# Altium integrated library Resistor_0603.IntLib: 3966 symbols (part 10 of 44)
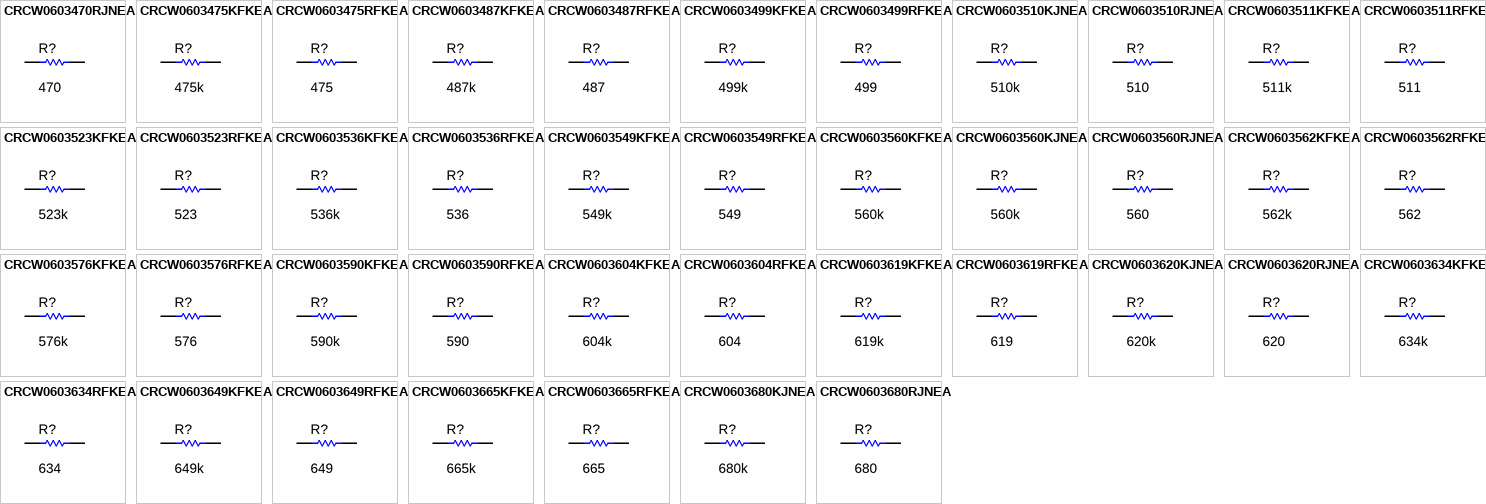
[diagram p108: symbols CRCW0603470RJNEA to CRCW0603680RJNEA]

## CRCW0603511KFKEA
designator R?  ValueDisplayed: 511k  (hidden comment: CRCW0603511KFKEA)
RES, 511 k, 1%, 0.1 W, 0603; Manufacturer: Vishay-Dale; CompType: Resistor; Value: 511k; Res_ohm: 511000; Tolerance_%: 1; Power_W: 0.1; Value2: 0.1W; VDC_V: 75; TempCo: 100 ppm/C; SizeArea_mm2: 1.28; SizeX_mm: 1.6; SizeY_mm: 0.8; EIA_Code: E96; U/M: EA; AEC Category: Q200; Green_Lifecycle: Active; Green_REACh: Passed
signal-integrity model Resistor
simulation model Resistor
footprint 0603
footprint 0603M
footprint 0603L
footprint 0603_HV
footprint 0603S
pins: 1, 2

## CRCW0603511RFKEA
designator R?  ValueDisplayed: 511  (hidden comment: CRCW0603511RFKEA)
RES, 511, 1%, 0.1 W, 0603; Manufacturer: Vishay-Dale; CompType: Resistor; Value: 511; Value_Code: 511R; Tolerance_%: 1; Power_W: 0.1; Value2: 0.1W; VDC_V: 75; TempCo: 100 ppm/C; SizeArea_mm2: 1.28; SizeX_mm: 1.6; SizeY_mm: 0.8; EIA_Code: E96; U/M: EA; AEC Category: Q200; Green_Lifecycle: Active; Green_REACh: Passed
signal-integrity model Resistor
simulation model Resistor
footprint 0603
footprint 0603M
footprint 0603L
footprint 0603_HV
footprint 0603S
pins: 1, 2

## CRCW0603523KFKEA
designator R?  ValueDisplayed: 523k  (hidden comment: CRCW0603523KFKEA)
RES, 523 k, 1%, 0.1 W, 0603; Manufacturer: Vishay-Dale; CompType: Resistor; Value: 523k; Res_ohm: 523000; Tolerance_%: 1; Power_W: 0.1; Value2: 0.1W; VDC_V: 75; TempCo: 100 ppm/C; SizeArea_mm2: 1.28; SizeX_mm: 1.6; SizeY_mm: 0.8; EIA_Code: E96; U/M: EA; AEC Category: Q200; Green_Lifecycle: Active; Green_REACh: Passed
signal-integrity model Resistor
simulation model Resistor
footprint 0603
footprint 0603M
footprint 0603L
footprint 0603_HV
footprint 0603S
pins: 1, 2

## CRCW0603523RFKEA
designator R?  ValueDisplayed: 523  (hidden comment: CRCW0603523RFKEA)
RES, 523, 1%, 0.1 W, 0603; Manufacturer: Vishay-Dale; CompType: Resistor; Value: 523; Value_Code: 523R; Tolerance_%: 1; Power_W: 0.1; Value2: 0.1W; VDC_V: 75; TempCo: 100 ppm/C; SizeArea_mm2: 1.28; SizeX_mm: 1.6; SizeY_mm: 0.8; EIA_Code: E96; U/M: EA; AEC Category: Q200
signal-integrity model Resistor
simulation model Resistor
footprint 0603
footprint 0603M
footprint 0603L
footprint 0603_HV
footprint 0603S
pins: 1, 2

## CRCW0603536KFKEA
designator R?  ValueDisplayed: 536k  (hidden comment: CRCW0603536KFKEA)
RES, 536 k, 1%, 0.1 W, 0603; Manufacturer: Vishay-Dale; CompType: Resistor; Value: 536k; Res_ohm: 536000; Tolerance_%: 1; Power_W: 0.1; Value2: 0.1W; VDC_V: 75; TempCo: 100 ppm/C; SizeArea_mm2: 1.28; SizeX_mm: 1.6; SizeY_mm: 0.8; EIA_Code: E96; U/M: EA; AEC Category: Q200
signal-integrity model Resistor
simulation model Resistor
footprint 0603
footprint 0603M
footprint 0603L
footprint 0603_HV
footprint 0603S
pins: 1, 2

## CRCW0603536RFKEA
designator R?  ValueDisplayed: 536  (hidden comment: CRCW0603536RFKEA)
RES, 536, 1%, 0.1 W, 0603; Manufacturer: Vishay-Dale; CompType: Resistor; Value: 536; Value_Code: 536R; Tolerance_%: 1; Power_W: 0.1; Value2: 0.1W; VDC_V: 75; TempCo: 100 ppm/C; SizeArea_mm2: 1.28; SizeX_mm: 1.6; SizeY_mm: 0.8; EIA_Code: E96; U/M: EA; AEC Category: Q200
signal-integrity model Resistor
simulation model Resistor
footprint 0603
footprint 0603M
footprint 0603L
footprint 0603_HV
footprint 0603S
pins: 1, 2

## CRCW0603549KFKEA
designator R?  ValueDisplayed: 549k  (hidden comment: CRCW0603549KFKEA)
RES, 549 k, 1%, 0.1 W, 0603; Manufacturer: Vishay-Dale; CompType: Resistor; Value: 549k; Res_ohm: 549000; Tolerance_%: 1; Power_W: 0.1; Value2: 0.1W; VDC_V: 75; TempCo: 100 ppm/C; SizeArea_mm2: 1.28; SizeX_mm: 1.6; SizeY_mm: 0.8; EIA_Code: E96; U/M: EA; AEC Category: Q200; Green_Lifecycle: Active; Green_REACh: Passed
signal-integrity model Resistor
simulation model Resistor
footprint 0603
footprint 0603M
footprint 0603L
footprint 0603_HV
footprint 0603S
pins: 1, 2

## CRCW0603549RFKEA
designator R?  ValueDisplayed: 549  (hidden comment: CRCW0603549RFKEA)
RES, 549, 1%, 0.1 W, 0603; Manufacturer: Vishay-Dale; CompType: Resistor; Value: 549; Value_Code: 549R; Tolerance_%: 1; Power_W: 0.1; Value2: 0.1W; VDC_V: 75; TempCo: 100 ppm/C; SizeArea_mm2: 1.28; SizeX_mm: 1.6; SizeY_mm: 0.8; EIA_Code: E96; U/M: EA; AEC Category: Q200; Green_Lifecycle: Active; Green_REACh: Passed
signal-integrity model Resistor
simulation model Resistor
footprint 0603
footprint 0603M
footprint 0603L
footprint 0603_HV
footprint 0603S
pins: 1, 2

## CRCW0603560KFKEA
designator R?  ValueDisplayed: 560k  (hidden comment: CRCW0603560KFKEA)
RES, 560 k, 1%, 0.1 W, AEC-Q200 Grade 0, 0603; Manufacturer: Vishay-Dale; CompType: Resistor; Value: 560k; Res_ohm: 560000; Tolerance_%: 1; Power_W: 0.1; Value2: 0.1W; VDC_V: 75; TempCo: 100 ppm/C; SizeArea_mm2: 1.28; SizeX_mm: 1.6; SizeY_mm: 0.8; U/M: EA; AEC Category: Q200; AEC Qualified: Y; AEC Grade: 0; Green_Lifecycle: Active; Green_REACh: Passed
signal-integrity model Resistor
simulation model Resistor
footprint 0603
footprint 0603M
footprint 0603L
footprint 0603_HV
footprint 0603S
pins: 1, 2

## CRCW0603560KJNEA
designator R?  ValueDisplayed: 560k  (hidden comment: CRCW0603560KJNEA)
RES, 560 k, 5%, 0.1 W, 0603; Manufacturer: Vishay-Dale; CompType: Resistor; Value: 560k; Res_ohm: 560000; Tolerance_%: 5; Power_W: 0.1; Value2: 0.1W; VDC_V: 75; TempCo: 200 ppm/C; SizeArea_mm2: 1.28; SizeX_mm: 1.6; SizeY_mm: 0.8; SizeZ_mm: 1; EIA_Code: E24; U/M: EA; AEC Category: Q200
signal-integrity model Resistor
simulation model Resistor
footprint 0603
footprint 0603M
footprint 0603L
footprint 0603_HV
footprint 0603S
pins: 1, 2

## CRCW0603560RJNEA
designator R?  ValueDisplayed: 560  (hidden comment: CRCW0603560RJNEA)
RES, 560, 5%, 0.1 W, 0603; Manufacturer: Vishay-Dale; CompType: Resistor; Value: 560; Value_Code: 560R; Tolerance_%: 5; Power_W: 0.1; Value2: 0.1W; VDC_V: 75; TempCo: 200 ppm/C; SizeArea_mm2: 1.28; SizeX_mm: 1.6; SizeY_mm: 0.8; SizeZ_mm: 1; EIA_Code: E24; U/M: EA; AEC Category: Q200; Green_Lifecycle: Active; Green_REACh: Passed
signal-integrity model Resistor
simulation model Resistor
footprint 0603
footprint 0603M
footprint 0603L
footprint 0603_HV
footprint 0603S
pins: 1, 2

## CRCW0603562KFKEA
designator R?  ValueDisplayed: 562k  (hidden comment: CRCW0603562KFKEA)
RES, 562 k, 1%, 0.1 W, 0603; Manufacturer: Vishay-Dale; CompType: Resistor; Value: 562k; Res_ohm: 562000; Tolerance_%: 1; Power_W: 0.1; Value2: 0.1W; VDC_V: 75; TempCo: 100 ppm/C; SizeArea_mm2: 1.28; SizeX_mm: 1.6; SizeY_mm: 0.8; EIA_Code: E96; U/M: EA; AEC Category: Q200
signal-integrity model Resistor
simulation model Resistor
footprint 0603
footprint 0603M
footprint 0603L
footprint 0603_HV
footprint 0603S
pins: 1, 2

## CRCW0603562RFKEA
designator R?  ValueDisplayed: 562  (hidden comment: CRCW0603562RFKEA)
RES, 562, 1%, 0.1 W, 0603; Manufacturer: Vishay-Dale; CompType: Resistor; Value: 562; Value_Code: 562R; Tolerance_%: 1; Power_W: 0.1; Value2: 0.1W; VDC_V: 75; TempCo: 100 ppm/C; SizeArea_mm2: 1.28; SizeX_mm: 1.6; SizeY_mm: 0.8; EIA_Code: E96; U/M: EA; AEC Category: Q200
signal-integrity model Resistor
simulation model Resistor
footprint 0603
footprint 0603M
footprint 0603L
footprint 0603_HV
footprint 0603S
pins: 1, 2

## CRCW0603576KFKEA
designator R?  ValueDisplayed: 576k  (hidden comment: CRCW0603576KFKEA)
RES, 576 k, 1%, 0.1 W, 0603; Manufacturer: Vishay-Dale; CompType: Resistor; Value: 576k; Res_ohm: 576000; Tolerance_%: 1; Power_W: 0.1; Value2: 0.1W; VDC_V: 75; TempCo: 100 ppm/C; SizeArea_mm2: 1.28; SizeX_mm: 1.6; SizeY_mm: 0.8; EIA_Code: E96; U/M: EA; AEC Category: Q200
signal-integrity model Resistor
simulation model Resistor
footprint 0603
footprint 0603M
footprint 0603L
footprint 0603_HV
footprint 0603S
pins: 1, 2

## CRCW0603576RFKEA
designator R?  ValueDisplayed: 576  (hidden comment: CRCW0603576RFKEA)
RES, 576, 1%, 0.1 W, 0603; Manufacturer: Vishay-Dale; CompType: Resistor; Value: 576; Value_Code: 576R; Tolerance_%: 1; Power_W: 0.1; Value2: 0.1W; VDC_V: 75; TempCo: 100 ppm/C; SizeArea_mm2: 1.28; SizeX_mm: 1.6; SizeY_mm: 0.8; EIA_Code: E96; U/M: EA; AEC Category: Q200; Green_Lifecycle: Active; Green_REACh: Passed
signal-integrity model Resistor
simulation model Resistor
footprint 0603
footprint 0603M
footprint 0603L
footprint 0603_HV
footprint 0603S
pins: 1, 2

## CRCW0603590KFKEA
designator R?  ValueDisplayed: 590k  (hidden comment: CRCW0603590KFKEA)
RES, 590 k, 1%, 0.1 W, 0603; Manufacturer: Vishay-Dale; CompType: Resistor; Value: 590k; Res_ohm: 590000; Tolerance_%: 1; Power_W: 0.1; Value2: 0.1W; VDC_V: 75; TempCo: 100 ppm/C; SizeArea_mm2: 1.28; SizeX_mm: 1.6; SizeY_mm: 0.8; EIA_Code: E96; U/M: EA; AEC Category: Q200; Green_Lifecycle: Active; Green_REACh: Passed
signal-integrity model Resistor
simulation model Resistor
footprint 0603
footprint 0603M
footprint 0603L
footprint 0603_HV
footprint 0603S
pins: 1, 2

## CRCW0603590RFKEA
designator R?  ValueDisplayed: 590  (hidden comment: CRCW0603590RFKEA)
RES, 590, 1%, 0.1 W, 0603; Manufacturer: Vishay-Dale; CompType: Resistor; Value: 590; Value_Code: 590R; Tolerance_%: 1; Power_W: 0.1; Value2: 0.1W; VDC_V: 75; TempCo: 100 ppm/C; SizeArea_mm2: 1.28; SizeX_mm: 1.6; SizeY_mm: 0.8; EIA_Code: E96; U/M: EA; AEC Category: Q200; Green_Lifecycle: Active; Green_REACh: Passed
signal-integrity model Resistor
simulation model Resistor
footprint 0603
footprint 0603M
footprint 0603L
footprint 0603_HV
footprint 0603S
pins: 1, 2

## CRCW0603604KFKEA
designator R?  ValueDisplayed: 604k  (hidden comment: CRCW0603604KFKEA)
RES, 604 k, 1%, 0.1 W, 0603; Manufacturer: Vishay-Dale; CompType: Resistor; Value: 604k; Res_ohm: 604000; Tolerance_%: 1; Power_W: 0.1; Value2: 0.1W; VDC_V: 75; TempCo: 100 ppm/C; SizeArea_mm2: 1.28; SizeX_mm: 1.6; SizeY_mm: 0.8; EIA_Code: E96; U/M: EA; AEC Category: Q200; Green_Lifecycle: Active; Green_REACh: Passed
signal-integrity model Resistor
simulation model Resistor
footprint 0603
footprint 0603M
footprint 0603L
footprint 0603_HV
footprint 0603S
pins: 1, 2

## CRCW0603604RFKEA
designator R?  ValueDisplayed: 604  (hidden comment: CRCW0603604RFKEA)
RES, 604, 1%, 0.1 W, 0603; Manufacturer: Vishay-Dale; CompType: Resistor; Value: 604; Value_Code: 604R; Tolerance_%: 1; Power_W: 0.1; Value2: 0.1W; VDC_V: 75; TempCo: 100 ppm/C; SizeArea_mm2: 1.28; SizeX_mm: 1.6; SizeY_mm: 0.8; EIA_Code: E96; U/M: EA; AEC Category: Q200; Green_Lifecycle: Active; Green_REACh: Passed
signal-integrity model Resistor
simulation model Resistor
footprint 0603
footprint 0603M
footprint 0603L
footprint 0603_HV
footprint 0603S
pins: 1, 2

## CRCW0603619KFKEA
designator R?  ValueDisplayed: 619k  (hidden comment: CRCW0603619KFKEA)
RES, 619 k, 1%, 0.1 W, 0603; Manufacturer: Vishay-Dale; CompType: Resistor; Value: 619k; Res_ohm: 619000; Tolerance_%: 1; Power_W: 0.1; Value2: 0.1W; VDC_V: 75; TempCo: 100 ppm/C; SizeArea_mm2: 1.28; SizeX_mm: 1.6; SizeY_mm: 0.8; EIA_Code: E96; U/M: EA; AEC Category: Q200; Green_Lifecycle: Active; Green_REACh: Passed
signal-integrity model Resistor
simulation model Resistor
footprint 0603
footprint 0603M
footprint 0603L
footprint 0603_HV
footprint 0603S
pins: 1, 2

## CRCW0603619RFKEA
designator R?  ValueDisplayed: 619  (hidden comment: CRCW0603619RFKEA)
RES, 619, 1%, 0.1 W, 0603; Manufacturer: Vishay-Dale; CompType: Resistor; Value: 619; Value_Code: 619R; Tolerance_%: 1; Power_W: 0.1; Value2: 0.1W; VDC_V: 75; TempCo: 100 ppm/C; SizeArea_mm2: 1.28; SizeX_mm: 1.6; SizeY_mm: 0.8; EIA_Code: E96; U/M: EA; AEC Category: Q200
signal-integrity model Resistor
simulation model Resistor
footprint 0603
footprint 0603M
footprint 0603L
footprint 0603_HV
footprint 0603S
pins: 1, 2

## CRCW0603620KJNEA
designator R?  ValueDisplayed: 620k  (hidden comment: CRCW0603620KJNEA)
RES, 620 k, 5%, 0.1 W, 0603; Manufacturer: Vishay-Dale; CompType: Resistor; Value: 620k; Res_ohm: 620000; Tolerance_%: 5; Power_W: 0.1; Value2: 0.1W; VDC_V: 75; TempCo: 200 ppm/C; SizeArea_mm2: 1.28; SizeX_mm: 1.6; SizeY_mm: 0.8; SizeZ_mm: 1; EIA_Code: E24; U/M: EA; AEC Category: Q200
signal-integrity model Resistor
simulation model Resistor
footprint 0603
footprint 0603M
footprint 0603L
footprint 0603_HV
footprint 0603S
pins: 1, 2

## CRCW0603620RJNEA
designator R?  ValueDisplayed: 620  (hidden comment: CRCW0603620RJNEA)
RES, 620, 5%, 0.1 W, 0603; Manufacturer: Vishay-Dale; CompType: Resistor; Value: 620; Value_Code: 620R; Tolerance_%: 5; Power_W: 0.1; Value2: 0.1W; VDC_V: 75; TempCo: 200 ppm/C; SizeArea_mm2: 1.28; SizeX_mm: 1.6; SizeY_mm: 0.8; SizeZ_mm: 1; EIA_Code: E24; U/M: EA; AEC Category: Q200; Green_Lifecycle: Active; Green_REACh: Passed
signal-integrity model Resistor
simulation model Resistor
footprint 0603
footprint 0603M
footprint 0603L
footprint 0603_HV
footprint 0603S
pins: 1, 2

## CRCW0603634KFKEA
designator R?  ValueDisplayed: 634k  (hidden comment: CRCW0603634KFKEA)
RES, 634 k, 1%, 0.1 W, 0603; Manufacturer: Vishay-Dale; CompType: Resistor; Value: 634k; Res_ohm: 634000; Tolerance_%: 1; Power_W: 0.1; Value2: 0.1W; VDC_V: 75; TempCo: 100 ppm/C; SizeArea_mm2: 1.28; SizeX_mm: 1.6; SizeY_mm: 0.8; EIA_Code: E96; U/M: EA; AEC Category: Q200
signal-integrity model Resistor
simulation model Resistor
footprint 0603
footprint 0603M
footprint 0603L
footprint 0603_HV
footprint 0603S
pins: 1, 2

## CRCW0603634RFKEA
designator R?  ValueDisplayed: 634  (hidden comment: CRCW0603634RFKEA)
RES, 634, 1%, 0.1 W, 0603; Manufacturer: Vishay-Dale; CompType: Resistor; Value: 634; Value_Code: 634R; Tolerance_%: 1; Power_W: 0.1; Value2: 0.1W; VDC_V: 75; TempCo: 100 ppm/C; SizeArea_mm2: 1.28; SizeX_mm: 1.6; SizeY_mm: 0.8; EIA_Code: E96; U/M: EA; AEC Category: Q200; Green_Lifecycle: Active; Green_REACh: Passed
signal-integrity model Resistor
simulation model Resistor
footprint 0603
footprint 0603M
footprint 0603L
footprint 0603_HV
footprint 0603S
pins: 1, 2

## CRCW0603649KFKEA
designator R?  ValueDisplayed: 649k  (hidden comment: CRCW0603649KFKEA)
RES, 649 k, 1%, 0.1 W, 0603; Manufacturer: Vishay-Dale; CompType: Resistor; Value: 649k; Res_ohm: 649000; Tolerance_%: 1; Power_W: 0.1; Value2: 0.1W; VDC_V: 75; TempCo: 100 ppm/C; SizeArea_mm2: 1.28; SizeX_mm: 1.6; SizeY_mm: 0.8; EIA_Code: E96; U/M: EA; AEC Category: Q200
signal-integrity model Resistor
simulation model Resistor
footprint 0603
footprint 0603M
footprint 0603L
footprint 0603_HV
footprint 0603S
pins: 1, 2

## CRCW0603649RFKEA
designator R?  ValueDisplayed: 649  (hidden comment: CRCW0603649RFKEA)
RES, 649, 1%, 0.1 W, 0603; Manufacturer: Vishay-Dale; CompType: Resistor; Value: 649; Value_Code: 649R; Tolerance_%: 1; Power_W: 0.1; Value2: 0.1W; VDC_V: 75; TempCo: 100 ppm/C; SizeArea_mm2: 1.28; SizeX_mm: 1.6; SizeY_mm: 0.8; EIA_Code: E96; U/M: EA; AEC Category: Q200; Green_Lifecycle: Active; Green_REACh: Passed
signal-integrity model Resistor
simulation model Resistor
footprint 0603
footprint 0603M
footprint 0603L
footprint 0603_HV
footprint 0603S
pins: 1, 2

## CRCW0603665KFKEA
designator R?  ValueDisplayed: 665k  (hidden comment: CRCW0603665KFKEA)
RES, 665 k, 1%, 0.1 W, 0603; Manufacturer: Vishay-Dale; CompType: Resistor; Value: 665k; Res_ohm: 665000; Tolerance_%: 1; Power_W: 0.1; Value2: 0.1W; VDC_V: 75; TempCo: 100 ppm/C; SizeArea_mm2: 1.28; SizeX_mm: 1.6; SizeY_mm: 0.8; EIA_Code: E96; U/M: EA; AEC Category: Q200
signal-integrity model Resistor
simulation model Resistor
footprint 0603
footprint 0603M
footprint 0603L
footprint 0603_HV
footprint 0603S
pins: 1, 2

## CRCW0603665RFKEA
designator R?  ValueDisplayed: 665  (hidden comment: CRCW0603665RFKEA)
RES, 665, 1%, 0.1 W, 0603; Manufacturer: Vishay-Dale; CompType: Resistor; Value: 665; Value_Code: 665R; Tolerance_%: 1; Power_W: 0.1; Value2: 0.1W; VDC_V: 75; TempCo: 100 ppm/C; SizeArea_mm2: 1.28; SizeX_mm: 1.6; SizeY_mm: 0.8; EIA_Code: E96; U/M: EA; AEC Category: Q200
signal-integrity model Resistor
simulation model Resistor
footprint 0603
footprint 0603M
footprint 0603L
footprint 0603_HV
footprint 0603S
pins: 1, 2

## CRCW0603680KJNEA
designator R?  ValueDisplayed: 680k  (hidden comment: CRCW0603680KJNEA)
RES, 680 k, 5%, 0.1 W, 0603; Manufacturer: Vishay-Dale; CompType: Resistor; Value: 680k; Res_ohm: 680000; Tolerance_%: 5; Power_W: 0.1; Value2: 0.1W; VDC_V: 75; TempCo: 200 ppm/C; SizeArea_mm2: 1.28; SizeX_mm: 1.6; SizeY_mm: 0.8; SizeZ_mm: 1; EIA_Code: E24; U/M: EA; AEC Category: Q200; Green_Lifecycle: Active; Green_REACh: Passed
signal-integrity model Resistor
simulation model Resistor
footprint 0603
footprint 0603M
footprint 0603L
footprint 0603_HV
footprint 0603S
pins: 1, 2

## CRCW0603680RJNEA
designator R?  ValueDisplayed: 680  (hidden comment: CRCW0603680RJNEA)
RES, 680, 5%, 0.1 W, 0603; Manufacturer: Vishay-Dale; CompType: Resistor; Value: 680; Value_Code: 680R; Tolerance_%: 5; Power_W: 0.1; Value2: 0.1W; VDC_V: 75; TempCo: 200 ppm/C; SizeArea_mm2: 1.28; SizeX_mm: 1.6; SizeY_mm: 0.8; SizeZ_mm: 1; EIA_Code: E24; U/M: EA; AEC Category: Q200; Green_Lifecycle: Active; Green_REACh: Passed
signal-integrity model Resistor
simulation model Resistor
footprint 0603
footprint 0603M
footprint 0603L
footprint 0603_HV
footprint 0603S
pins: 1, 2

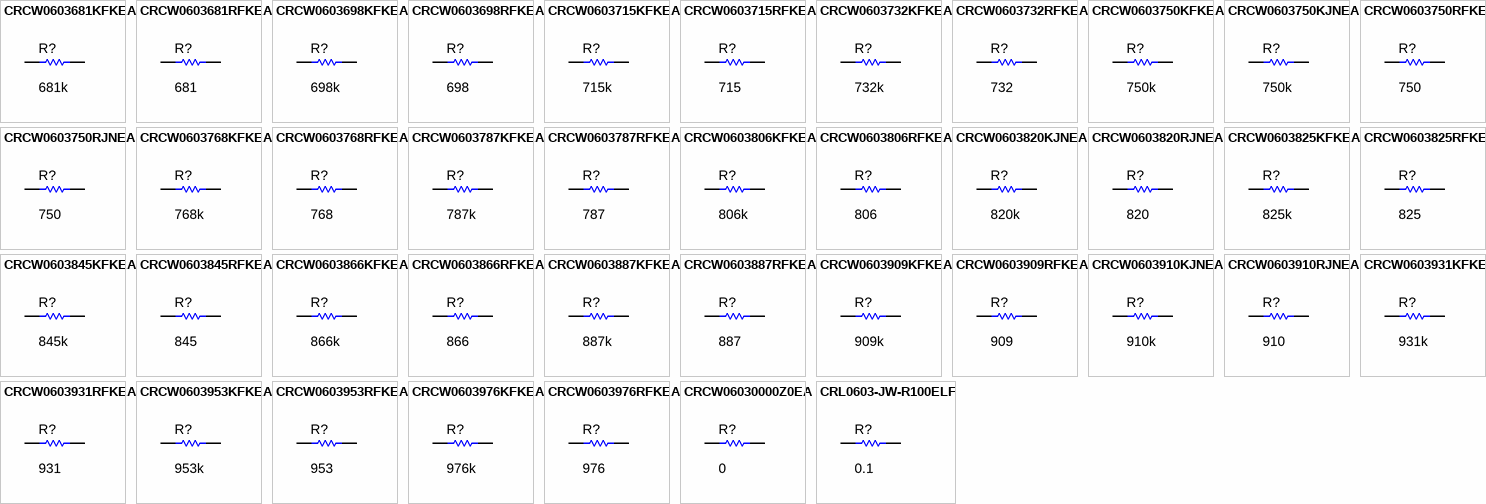
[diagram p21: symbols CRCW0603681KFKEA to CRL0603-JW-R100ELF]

## CRCW0603681KFKEA
designator R?  ValueDisplayed: 681k  (hidden comment: CRCW0603681KFKEA)
RES, 681 k, 1%, 0.1 W, 0603; Manufacturer: Vishay-Dale; CompType: Resistor; Value: 681k; Res_ohm: 681000; Tolerance_%: 1; Power_W: 0.1; Value2: 0.1W; VDC_V: 75; TempCo: 100 ppm/C; SizeArea_mm2: 1.28; SizeX_mm: 1.6; SizeY_mm: 0.8; EIA_Code: E96; U/M: EA; AEC Category: Q200; Green_Lifecycle: Active; Green_REACh: Passed
signal-integrity model Resistor
simulation model Resistor
footprint 0603
footprint 0603M
footprint 0603L
footprint 0603_HV
footprint 0603S
pins: 1, 2

## CRCW0603681RFKEA
designator R?  ValueDisplayed: 681  (hidden comment: CRCW0603681RFKEA)
RES, 681, 1%, 0.1 W, 0603; Manufacturer: Vishay-Dale; CompType: Resistor; Value: 681; Value_Code: 681R; Tolerance_%: 1; Power_W: 0.1; Value2: 0.1W; VDC_V: 75; TempCo: 100 ppm/C; SizeArea_mm2: 1.28; SizeX_mm: 1.6; SizeY_mm: 0.8; EIA_Code: E96; U/M: EA; AEC Category: Q200; Green_Lifecycle: Active; Green_REACh: Passed
signal-integrity model Resistor
simulation model Resistor
footprint 0603
footprint 0603M
footprint 0603L
footprint 0603_HV
footprint 0603S
pins: 1, 2

## CRCW0603698KFKEA
designator R?  ValueDisplayed: 698k  (hidden comment: CRCW0603698KFKEA)
RES, 698 k, 1%, 0.1 W, 0603; Manufacturer: Vishay-Dale; CompType: Resistor; Value: 698k; Res_ohm: 698000; Tolerance_%: 1; Power_W: 0.1; Value2: 0.1W; VDC_V: 75; TempCo: 100 ppm/C; SizeArea_mm2: 1.28; SizeX_mm: 1.6; SizeY_mm: 0.8; EIA_Code: E96; U/M: EA; AEC Category: Q200
signal-integrity model Resistor
simulation model Resistor
footprint 0603
footprint 0603M
footprint 0603L
footprint 0603_HV
footprint 0603S
pins: 1, 2

## CRCW0603698RFKEA
designator R?  ValueDisplayed: 698  (hidden comment: CRCW0603698RFKEA)
RES, 698, 1%, 0.1 W, 0603; Manufacturer: Vishay-Dale; CompType: Resistor; Value: 698; Value_Code: 698R; Tolerance_%: 1; Power_W: 0.1; Value2: 0.1W; VDC_V: 75; TempCo: 100 ppm/C; SizeArea_mm2: 1.28; SizeX_mm: 1.6; SizeY_mm: 0.8; EIA_Code: E96; U/M: EA; AEC Category: Q200
signal-integrity model Resistor
simulation model Resistor
footprint 0603
footprint 0603M
footprint 0603L
footprint 0603_HV
footprint 0603S
pins: 1, 2

## CRCW0603715KFKEA
designator R?  ValueDisplayed: 715k  (hidden comment: CRCW0603715KFKEA)
RES, 715 k, 1%, 0.1 W, 0603; Manufacturer: Vishay-Dale; CompType: Resistor; Value: 715k; Res_ohm: 715000; Tolerance_%: 1; Power_W: 0.1; Value2: 0.1W; VDC_V: 75; TempCo: 100 ppm/C; SizeArea_mm2: 1.28; SizeX_mm: 1.6; SizeY_mm: 0.8; EIA_Code: E96; U/M: EA; AEC Category: Q200
signal-integrity model Resistor
simulation model Resistor
footprint 0603
footprint 0603M
footprint 0603L
footprint 0603_HV
footprint 0603S
pins: 1, 2

## CRCW0603715RFKEA
designator R?  ValueDisplayed: 715  (hidden comment: CRCW0603715RFKEA)
RES, 715, 1%, 0.1 W, 0603; Manufacturer: Vishay-Dale; CompType: Resistor; Value: 715; Value_Code: 715R; Tolerance_%: 1; Power_W: 0.1; Value2: 0.1W; VDC_V: 75; TempCo: 100 ppm/C; SizeArea_mm2: 1.28; SizeX_mm: 1.6; SizeY_mm: 0.8; EIA_Code: E96; U/M: EA; AEC Category: Q200; Green_Lifecycle: Active; Green_REACh: Passed
signal-integrity model Resistor
simulation model Resistor
footprint 0603
footprint 0603M
footprint 0603L
footprint 0603_HV
footprint 0603S
pins: 1, 2

## CRCW0603732KFKEA
designator R?  ValueDisplayed: 732k  (hidden comment: CRCW0603732KFKEA)
RES, 732 k, 1%, 0.1 W, 0603; Manufacturer: Vishay-Dale; CompType: Resistor; Value: 732k; Res_ohm: 732000; Tolerance_%: 1; Power_W: 0.1; Value2: 0.1W; VDC_V: 75; TempCo: 100 ppm/C; SizeArea_mm2: 1.28; SizeX_mm: 1.6; SizeY_mm: 0.8; EIA_Code: E96; U/M: EA; AEC Category: Q200; Green_Lifecycle: Active; Green_REACh: Passed
signal-integrity model Resistor
simulation model Resistor
footprint 0603
footprint 0603M
footprint 0603L
footprint 0603_HV
footprint 0603S
pins: 1, 2

## CRCW0603732RFKEA
designator R?  ValueDisplayed: 732  (hidden comment: CRCW0603732RFKEA)
RES, 732, 1%, 0.1 W, 0603; Manufacturer: Vishay-Dale; CompType: Resistor; Value: 732; Value_Code: 732R; Tolerance_%: 1; Power_W: 0.1; Value2: 0.1W; VDC_V: 75; TempCo: 100 ppm/C; SizeArea_mm2: 1.28; SizeX_mm: 1.6; SizeY_mm: 0.8; EIA_Code: E96; U/M: EA; AEC Category: Q200; Green_Lifecycle: Active; Green_REACh: Passed
signal-integrity model Resistor
simulation model Resistor
footprint 0603
footprint 0603M
footprint 0603L
footprint 0603_HV
footprint 0603S
pins: 1, 2

## CRCW0603750KFKEA
designator R?  ValueDisplayed: 750k  (hidden comment: CRCW0603750KFKEA)
RES, 750 k, 1%, 0.1 W, 0603; Manufacturer: Vishay-Dale; CompType: Resistor; Value: 750k; Res_ohm: 750000; Tolerance_%: 1; Power_W: 0.1; Value2: 0.1W; VDC_V: 75; TempCo: 100 ppm/C; SizeArea_mm2: 1.28; SizeX_mm: 1.6; SizeY_mm: 0.8; EIA_Code: E96; U/M: EA; AEC Category: Q200; Green_Lifecycle: Active; Green_REACh: Passed
signal-integrity model Resistor
simulation model Resistor
footprint 0603
footprint 0603M
footprint 0603L
footprint 0603_HV
footprint 0603S
pins: 1, 2

## CRCW0603750KJNEA
designator R?  ValueDisplayed: 750k  (hidden comment: CRCW0603750KJNEA)
RES, 750 k, 5%, 0.1 W, 0603; Manufacturer: Vishay-Dale; CompType: Resistor; Value: 750k; Res_ohm: 750000; Tolerance_%: 5; Power_W: 0.1; Value2: 0.1W; VDC_V: 75; TempCo: 200 ppm/C; SizeArea_mm2: 1.28; SizeX_mm: 1.6; SizeY_mm: 0.8; SizeZ_mm: 1; EIA_Code: E24; U/M: EA; AEC Category: Q200
signal-integrity model Resistor
simulation model Resistor
footprint 0603
footprint 0603M
footprint 0603L
footprint 0603_HV
footprint 0603S
pins: 1, 2

## CRCW0603750RFKEA
designator R?  ValueDisplayed: 750  (hidden comment: CRCW0603750RFKEA)
RES, 750, 1%, 0.1 W, 0603; Manufacturer: Vishay-Dale; CompType: Resistor; Value: 750; Value_Code: 750R; Tolerance_%: 1; Power_W: 0.1; Value2: 0.1W; VDC_V: 75; TempCo: 100 ppm/C; SizeArea_mm2: 1.28; SizeX_mm: 1.6; SizeY_mm: 0.8; EIA_Code: E96; U/M: EA; AEC Category: Q200; Green_Lifecycle: Active; Green_REACh: Passed
signal-integrity model Resistor
simulation model Resistor
footprint 0603
footprint 0603M
footprint 0603L
footprint 0603_HV
footprint 0603S
pins: 1, 2

## CRCW0603750RJNEA
designator R?  ValueDisplayed: 750  (hidden comment: CRCW0603750RJNEA)
RES, 750, 5%, 0.1 W, 0603; Manufacturer: Vishay-Dale; CompType: Resistor; Value: 750; Value_Code: 750R; Tolerance_%: 5; Power_W: 0.1; Value2: 0.1W; VDC_V: 75; TempCo: 200 ppm/C; SizeArea_mm2: 1.28; SizeX_mm: 1.6; SizeY_mm: 0.8; SizeZ_mm: 1; EIA_Code: E24; U/M: EA; AEC Category: Q200
signal-integrity model Resistor
simulation model Resistor
footprint 0603
footprint 0603M
footprint 0603L
footprint 0603_HV
footprint 0603S
pins: 1, 2

## CRCW0603768KFKEA
designator R?  ValueDisplayed: 768k  (hidden comment: CRCW0603768KFKEA)
RES, 768 k, 1%, 0.1 W, 0603; Manufacturer: Vishay-Dale; CompType: Resistor; Value: 768k; Res_ohm: 768000; Tolerance_%: 1; Power_W: 0.1; Value2: 0.1W; VDC_V: 75; TempCo: 100 ppm/C; SizeArea_mm2: 1.28; SizeX_mm: 1.6; SizeY_mm: 0.8; EIA_Code: E96; U/M: EA; AEC Category: Q200
signal-integrity model Resistor
simulation model Resistor
footprint 0603
footprint 0603M
footprint 0603L
footprint 0603_HV
footprint 0603S
pins: 1, 2

## CRCW0603768RFKEA
designator R?  ValueDisplayed: 768  (hidden comment: CRCW0603768RFKEA)
RES, 768, 1%, 0.1 W, 0603; Manufacturer: Vishay-Dale; CompType: Resistor; Value: 768; Value_Code: 768R; Tolerance_%: 1; Power_W: 0.1; Value2: 0.1W; VDC_V: 75; TempCo: 100 ppm/C; SizeArea_mm2: 1.28; SizeX_mm: 1.6; SizeY_mm: 0.8; EIA_Code: E96; U/M: EA; AEC Category: Q200; Green_Lifecycle: Active; Green_REACh: Passed
signal-integrity model Resistor
simulation model Resistor
footprint 0603
footprint 0603M
footprint 0603L
footprint 0603_HV
footprint 0603S
pins: 1, 2

## CRCW0603787KFKEA
designator R?  ValueDisplayed: 787k  (hidden comment: CRCW0603787KFKEA)
RES, 787 k, 1%, 0.1 W, 0603; Manufacturer: Vishay-Dale; CompType: Resistor; Value: 787k; Res_ohm: 787000; Tolerance_%: 1; Power_W: 0.1; Value2: 0.1W; VDC_V: 75; TempCo: 100 ppm/C; SizeArea_mm2: 1.28; SizeX_mm: 1.6; SizeY_mm: 0.8; EIA_Code: E96; U/M: EA; AEC Category: Q200
signal-integrity model Resistor
simulation model Resistor
footprint 0603
footprint 0603M
footprint 0603L
footprint 0603_HV
footprint 0603S
pins: 1, 2

## CRCW0603787RFKEA
designator R?  ValueDisplayed: 787  (hidden comment: CRCW0603787RFKEA)
RES, 787, 1%, 0.1 W, 0603; Manufacturer: Vishay-Dale; CompType: Resistor; Value: 787; Value_Code: 787R; Tolerance_%: 1; Power_W: 0.1; Value2: 0.1W; VDC_V: 75; TempCo: 100 ppm/C; SizeArea_mm2: 1.28; SizeX_mm: 1.6; SizeY_mm: 0.8; EIA_Code: E96; U/M: EA; AEC Category: Q200; Green_Lifecycle: Active; Green_REACh: Passed
signal-integrity model Resistor
simulation model Resistor
footprint 0603
footprint 0603M
footprint 0603L
footprint 0603_HV
footprint 0603S
pins: 1, 2

## CRCW0603806KFKEA
designator R?  ValueDisplayed: 806k  (hidden comment: CRCW0603806KFKEA)
RES, 806 k, 1%, 0.1 W, 0603; Manufacturer: Vishay-Dale; CompType: Resistor; Value: 806k; Res_ohm: 806000; Tolerance_%: 1; Power_W: 0.1; Value2: 0.1W; VDC_V: 75; TempCo: 100 ppm/C; SizeArea_mm2: 1.28; SizeX_mm: 1.6; SizeY_mm: 0.8; EIA_Code: E96; U/M: EA; AEC Category: Q200; Green_Lifecycle: Active; Green_REACh: Passed
signal-integrity model Resistor
simulation model Resistor
footprint 0603
footprint 0603M
footprint 0603L
footprint 0603_HV
footprint 0603S
pins: 1, 2

## CRCW0603806RFKEA
designator R?  ValueDisplayed: 806  (hidden comment: CRCW0603806RFKEA)
RES, 806, 1%, 0.1 W, 0603; Manufacturer: Vishay-Dale; CompType: Resistor; Value: 806; Value_Code: 806R; Tolerance_%: 1; Power_W: 0.1; Value2: 0.1W; VDC_V: 75; TempCo: 100 ppm/C; SizeArea_mm2: 1.28; SizeX_mm: 1.6; SizeY_mm: 0.8; EIA_Code: E96; U/M: EA; AEC Category: Q200; Green_Lifecycle: Active; Green_REACh: Passed
signal-integrity model Resistor
simulation model Resistor
footprint 0603
footprint 0603M
footprint 0603L
footprint 0603_HV
footprint 0603S
pins: 1, 2

## CRCW0603820KJNEA
designator R?  ValueDisplayed: 820k  (hidden comment: CRCW0603820KJNEA)
RES, 820 k, 5%, 0.1 W, 0603; Manufacturer: Vishay-Dale; CompType: Resistor; Value: 820k; Res_ohm: 820000; Tolerance_%: 5; Power_W: 0.1; Value2: 0.1W; VDC_V: 75; TempCo: 200 ppm/C; SizeArea_mm2: 1.28; SizeX_mm: 1.6; SizeY_mm: 0.8; SizeZ_mm: 1; EIA_Code: E24; U/M: EA; AEC Category: Q200
signal-integrity model Resistor
simulation model Resistor
footprint 0603
footprint 0603M
footprint 0603L
footprint 0603_HV
footprint 0603S
pins: 1, 2

## CRCW0603820RJNEA
designator R?  ValueDisplayed: 820  (hidden comment: CRCW0603820RJNEA)
RES, 820, 5%, 0.1 W, 0603; Manufacturer: Vishay-Dale; CompType: Resistor; Value: 820; Value_Code: 820R; Tolerance_%: 5; Power_W: 0.1; Value2: 0.1W; VDC_V: 75; TempCo: 200 ppm/C; SizeArea_mm2: 1.28; SizeX_mm: 1.6; SizeY_mm: 0.8; SizeZ_mm: 1; EIA_Code: E24; U/M: EA; AEC Category: Q200; Green_Lifecycle: Active; Green_REACh: Passed
signal-integrity model Resistor
simulation model Resistor
footprint 0603
footprint 0603M
footprint 0603L
footprint 0603_HV
footprint 0603S
pins: 1, 2

## CRCW0603825KFKEA
designator R?  ValueDisplayed: 825k  (hidden comment: CRCW0603825KFKEA)
RES, 825 k, 1%, 0.1 W, 0603; Manufacturer: Vishay-Dale; CompType: Resistor; Value: 825k; Res_ohm: 825000; Tolerance_%: 1; Power_W: 0.1; Value2: 0.1W; VDC_V: 75; TempCo: 100 ppm/C; SizeArea_mm2: 1.28; SizeX_mm: 1.6; SizeY_mm: 0.8; EIA_Code: E96; U/M: EA; AEC Category: Q200; Green_Lifecycle: Active; Green_REACh: Passed
signal-integrity model Resistor
simulation model Resistor
footprint 0603
footprint 0603M
footprint 0603L
footprint 0603_HV
footprint 0603S
pins: 1, 2

## CRCW0603825RFKEA
designator R?  ValueDisplayed: 825  (hidden comment: CRCW0603825RFKEA)
RES, 825, 1%, 0.1 W, 0603; Manufacturer: Vishay-Dale; CompType: Resistor; Value: 825; Value_Code: 825R; Tolerance_%: 1; Power_W: 0.1; Value2: 0.1W; VDC_V: 75; TempCo: 100 ppm/C; SizeArea_mm2: 1.28; SizeX_mm: 1.6; SizeY_mm: 0.8; EIA_Code: E96; U/M: EA; AEC Category: Q200; Green_Lifecycle: Active; Green_REACh: Passed
signal-integrity model Resistor
simulation model Resistor
footprint 0603
footprint 0603M
footprint 0603L
footprint 0603_HV
footprint 0603S
pins: 1, 2

## CRCW0603845KFKEA
designator R?  ValueDisplayed: 845k  (hidden comment: CRCW0603845KFKEA)
RES, 845 k, 1%, 0.1 W, 0603; Manufacturer: Vishay-Dale; CompType: Resistor; Value: 845k; Res_ohm: 845000; Tolerance_%: 1; Power_W: 0.1; Value2: 0.1W; VDC_V: 75; TempCo: 100 ppm/C; SizeArea_mm2: 1.28; SizeX_mm: 1.6; SizeY_mm: 0.8; EIA_Code: E96; U/M: EA; AEC Category: Q200; Green_Lifecycle: Active; Green_REACh: Passed
signal-integrity model Resistor
simulation model Resistor
footprint 0603
footprint 0603M
footprint 0603L
footprint 0603_HV
footprint 0603S
pins: 1, 2

## CRCW0603845RFKEA
designator R?  ValueDisplayed: 845  (hidden comment: CRCW0603845RFKEA)
RES, 845, 1%, 0.1 W, 0603; Manufacturer: Vishay-Dale; CompType: Resistor; Value: 845; Value_Code: 845R; Tolerance_%: 1; Power_W: 0.1; Value2: 0.1W; VDC_V: 75; TempCo: 100 ppm/C; SizeArea_mm2: 1.28; SizeX_mm: 1.6; SizeY_mm: 0.8; EIA_Code: E96; U/M: EA; AEC Category: Q200
signal-integrity model Resistor
simulation model Resistor
footprint 0603
footprint 0603M
footprint 0603L
footprint 0603_HV
footprint 0603S
pins: 1, 2

## CRCW0603866KFKEA
designator R?  ValueDisplayed: 866k  (hidden comment: CRCW0603866KFKEA)
RES, 866 k, 1%, 0.1 W, 0603; Manufacturer: Vishay-Dale; CompType: Resistor; Value: 866k; Res_ohm: 866000; Tolerance_%: 1; Power_W: 0.1; Value2: 0.1W; VDC_V: 75; TempCo: 100 ppm/C; SizeArea_mm2: 1.28; SizeX_mm: 1.6; SizeY_mm: 0.8; EIA_Code: E96; U/M: EA; AEC Category: Q200; Green_Lifecycle: Active; Green_REACh: Passed
signal-integrity model Resistor
simulation model Resistor
footprint 0603
footprint 0603M
footprint 0603L
footprint 0603_HV
footprint 0603S
pins: 1, 2

## CRCW0603866RFKEA
designator R?  ValueDisplayed: 866  (hidden comment: CRCW0603866RFKEA)
RES, 866, 1%, 0.1 W, 0603; Manufacturer: Vishay-Dale; CompType: Resistor; Value: 866; Value_Code: 866R; Tolerance_%: 1; Power_W: 0.1; Value2: 0.1W; VDC_V: 75; TempCo: 100 ppm/C; SizeArea_mm2: 1.28; SizeX_mm: 1.6; SizeY_mm: 0.8; EIA_Code: E96; U/M: EA; AEC Category: Q200; Green_Lifecycle: Active; Green_REACh: Passed
signal-integrity model Resistor
simulation model Resistor
footprint 0603
footprint 0603M
footprint 0603L
footprint 0603_HV
footprint 0603S
pins: 1, 2

## CRCW0603887KFKEA
designator R?  ValueDisplayed: 887k  (hidden comment: CRCW0603887KFKEA)
RES, 887 k, 1%, 0.1 W, 0603; Manufacturer: Vishay-Dale; CompType: Resistor; Value: 887k; Res_ohm: 887000; Tolerance_%: 1; Power_W: 0.1; Value2: 0.1W; VDC_V: 75; TempCo: 100 ppm/C; SizeArea_mm2: 1.28; SizeX_mm: 1.6; SizeY_mm: 0.8; EIA_Code: E96; U/M: EA; AEC Category: Q200; Green_Lifecycle: Active; Green_REACh: Passed
signal-integrity model Resistor
simulation model Resistor
footprint 0603
footprint 0603M
footprint 0603L
footprint 0603_HV
footprint 0603S
pins: 1, 2

## CRCW0603887RFKEA
designator R?  ValueDisplayed: 887  (hidden comment: CRCW0603887RFKEA)
RES, 887, 1%, 0.1 W, 0603; Manufacturer: Vishay-Dale; CompType: Resistor; Value: 887; Value_Code: 887R; Tolerance_%: 1; Power_W: 0.1; Value2: 0.1W; VDC_V: 75; TempCo: 100 ppm/C; SizeArea_mm2: 1.28; SizeX_mm: 1.6; SizeY_mm: 0.8; EIA_Code: E96; U/M: EA; AEC Category: Q200
signal-integrity model Resistor
simulation model Resistor
footprint 0603
footprint 0603M
footprint 0603L
footprint 0603_HV
footprint 0603S
pins: 1, 2

## CRCW0603909KFKEA
designator R?  ValueDisplayed: 909k  (hidden comment: CRCW0603909KFKEA)
RES, 909 k, 1%, 0.1 W, 0603; Manufacturer: Vishay-Dale; CompType: Resistor; Value: 909k; Res_ohm: 909000; Tolerance_%: 1; Power_W: 0.1; Value2: 0.1W; VDC_V: 75; TempCo: 100 ppm/C; SizeArea_mm2: 1.28; SizeX_mm: 1.6; SizeY_mm: 0.8; EIA_Code: E96; U/M: EA; AEC Category: Q200
signal-integrity model Resistor
simulation model Resistor
footprint 0603
footprint 0603M
footprint 0603L
footprint 0603_HV
footprint 0603S
pins: 1, 2

## CRCW0603909RFKEA
designator R?  ValueDisplayed: 909  (hidden comment: CRCW0603909RFKEA)
RES, 909, 1%, 0.1 W, 0603; Manufacturer: Vishay-Dale; CompType: Resistor; Value: 909; Value_Code: 909R; Tolerance_%: 1; Power_W: 0.1; Value2: 0.1W; VDC_V: 75; TempCo: 100 ppm/C; SizeArea_mm2: 1.28; SizeX_mm: 1.6; SizeY_mm: 0.8; EIA_Code: E96; U/M: EA; AEC Category: Q200
signal-integrity model Resistor
simulation model Resistor
footprint 0603
footprint 0603M
footprint 0603L
footprint 0603_HV
footprint 0603S
pins: 1, 2

## CRCW0603910KJNEA
designator R?  ValueDisplayed: 910k  (hidden comment: CRCW0603910KJNEA)
RES, 910 k, 5%, 0.1 W, 0603; Manufacturer: Vishay-Dale; CompType: Resistor; Value: 910k; Res_ohm: 910000; Tolerance_%: 5; Power_W: 0.1; Value2: 0.1W; VDC_V: 75; TempCo: 200 ppm/C; SizeArea_mm2: 1.28; SizeX_mm: 1.6; SizeY_mm: 0.8; SizeZ_mm: 1; EIA_Code: E24; U/M: EA; AEC Category: Q200; Green_Lifecycle: Active; Green_REACh: Passed
signal-integrity model Resistor
simulation model Resistor
footprint 0603
footprint 0603M
footprint 0603L
footprint 0603_HV
footprint 0603S
pins: 1, 2

## CRCW0603910RJNEA
designator R?  ValueDisplayed: 910  (hidden comment: CRCW0603910RJNEA)
RES, 910, 5%, 0.1 W, 0603; Manufacturer: Vishay-Dale; CompType: Resistor; Value: 910; Value_Code: 910R; Tolerance_%: 5; Power_W: 0.1; Value2: 0.1W; VDC_V: 75; TempCo: 200 ppm/C; SizeArea_mm2: 1.28; SizeX_mm: 1.6; SizeY_mm: 0.8; SizeZ_mm: 1; EIA_Code: E24; U/M: EA; AEC Category: Q200; Green_Lifecycle: Active; Green_REACh: Passed
signal-integrity model Resistor
simulation model Resistor
footprint 0603
footprint 0603M
footprint 0603L
footprint 0603_HV
footprint 0603S
pins: 1, 2

## CRCW0603931KFKEA
designator R?  ValueDisplayed: 931k  (hidden comment: CRCW0603931KFKEA)
RES, 931 k, 1%, 0.1 W, 0603; Manufacturer: Vishay-Dale; CompType: Resistor; Value: 931k; Res_ohm: 931000; Tolerance_%: 1; Power_W: 0.1; Value2: 0.1W; VDC_V: 75; TempCo: 100 ppm/C; SizeArea_mm2: 1.28; SizeX_mm: 1.6; SizeY_mm: 0.8; EIA_Code: E96; U/M: EA; AEC Category: Q200
signal-integrity model Resistor
simulation model Resistor
footprint 0603
footprint 0603M
footprint 0603L
footprint 0603_HV
footprint 0603S
pins: 1, 2

## CRCW0603931RFKEA
designator R?  ValueDisplayed: 931  (hidden comment: CRCW0603931RFKEA)
RES, 931, 1%, 0.1 W, 0603; Manufacturer: Vishay-Dale; CompType: Resistor; Value: 931; Value_Code: 931R; Tolerance_%: 1; Power_W: 0.1; Value2: 0.1W; VDC_V: 75; TempCo: 100 ppm/C; SizeArea_mm2: 1.28; SizeX_mm: 1.6; SizeY_mm: 0.8; EIA_Code: E96; U/M: EA; AEC Category: Q200
signal-integrity model Resistor
simulation model Resistor
footprint 0603
footprint 0603M
footprint 0603L
footprint 0603_HV
footprint 0603S
pins: 1, 2

## CRCW0603953KFKEA
designator R?  ValueDisplayed: 953k  (hidden comment: CRCW0603953KFKEA)
RES, 953 k, 1%, 0.1 W, 0603; Manufacturer: Vishay-Dale; CompType: Resistor; Value: 953k; Res_ohm: 953000; Tolerance_%: 1; Power_W: 0.1; Value2: 0.1W; VDC_V: 75; TempCo: 100 ppm/C; SizeArea_mm2: 1.28; SizeX_mm: 1.6; SizeY_mm: 0.8; EIA_Code: E96; U/M: EA; AEC Category: Q200
signal-integrity model Resistor
simulation model Resistor
footprint 0603
footprint 0603M
footprint 0603L
footprint 0603_HV
footprint 0603S
pins: 1, 2

## CRCW0603953RFKEA
designator R?  ValueDisplayed: 953  (hidden comment: CRCW0603953RFKEA)
RES, 953, 1%, 0.1 W, 0603; Manufacturer: Vishay-Dale; CompType: Resistor; Value: 953; Value_Code: 953R; Tolerance_%: 1; Power_W: 0.1; Value2: 0.1W; VDC_V: 75; TempCo: 100 ppm/C; SizeArea_mm2: 1.28; SizeX_mm: 1.6; SizeY_mm: 0.8; EIA_Code: E96; U/M: EA; AEC Category: Q200
signal-integrity model Resistor
simulation model Resistor
footprint 0603
footprint 0603M
footprint 0603L
footprint 0603_HV
footprint 0603S
pins: 1, 2

## CRCW0603976KFKEA
designator R?  ValueDisplayed: 976k  (hidden comment: CRCW0603976KFKEA)
RES, 976 k, 1%, 0.1 W, 0603; Manufacturer: Vishay-Dale; CompType: Resistor; Value: 976k; Res_ohm: 976000; Tolerance_%: 1; Power_W: 0.1; Value2: 0.1W; VDC_V: 75; TempCo: 100 ppm/C; SizeArea_mm2: 1.28; SizeX_mm: 1.6; SizeY_mm: 0.8; EIA_Code: E96; U/M: EA; AEC Category: Q200
signal-integrity model Resistor
simulation model Resistor
footprint 0603
footprint 0603M
footprint 0603L
footprint 0603_HV
footprint 0603S
pins: 1, 2

## CRCW0603976RFKEA
designator R?  ValueDisplayed: 976  (hidden comment: CRCW0603976RFKEA)
RES, 976, 1%, 0.1 W, 0603; Manufacturer: Vishay-Dale; CompType: Resistor; Value: 976; Value_Code: 976R; Tolerance_%: 1; Power_W: 0.1; Value2: 0.1W; VDC_V: 75; TempCo: 100 ppm/C; SizeArea_mm2: 1.28; SizeX_mm: 1.6; SizeY_mm: 0.8; EIA_Code: E96; U/M: EA; AEC Category: Q200; Green_Lifecycle: Active; Green_REACh: Passed
signal-integrity model Resistor
simulation model Resistor
footprint 0603
footprint 0603M
footprint 0603L
footprint 0603_HV
footprint 0603S
pins: 1, 2

## CRCW06030000Z0EA
designator R?  ValueDisplayed: 0  (hidden comment: CRCW06030000Z0EA)
RES, 0, 5%, 0.1 W, 0603; Manufacturer: Vishay-Dale; CompType: Resistor; Value: 0; Value_Code: 0000; Tolerance_%: 5; Power_W: 0.1; Value2: 0.1W; VDC_V: 75; TempCo: 200 ppm/C; SizeArea_mm2: 1.28; SizeX_mm: 1.6; SizeY_mm: 0.8; SizeZ_mm: 1; EIA_Code: E24; U/M: EA; AEC Category: Q200; Green_Lifecycle: Active; Green_REACh: Passed
signal-integrity model Resistor
simulation model Resistor
footprint 0603
footprint 0603M
footprint 0603L
footprint 0603_HV
footprint 0603S
pins: 1, 2

## CRL0603-JW-R100ELF
designator R?  ValueDisplayed: 0.1  (hidden comment: CRL0603-JW-R100ELF)
RES, 0.1, 5%, 0.1 W, 0603; Manufacturer: Bourns; CompType: Resistor; Value: 0.1; Value_Code: R100; Tolerance_%: 5; Value2: 0.1W; VDC_V: 0; TempCo: 200 ppm/C; SizeArea_mm2: 1.28; SizeX_mm: 1.6; SizeY_mm: 0.8; SizeZ_mm: 1; EIA_Code: E24; U/M: EA; AEC Category: Q200; AEC Qualified: N
signal-integrity model Resistor
simulation model Resistor
footprint 0603
footprint 0603M
footprint 0603L
footprint 0603_HV
footprint 0603S
pins: 1, 2

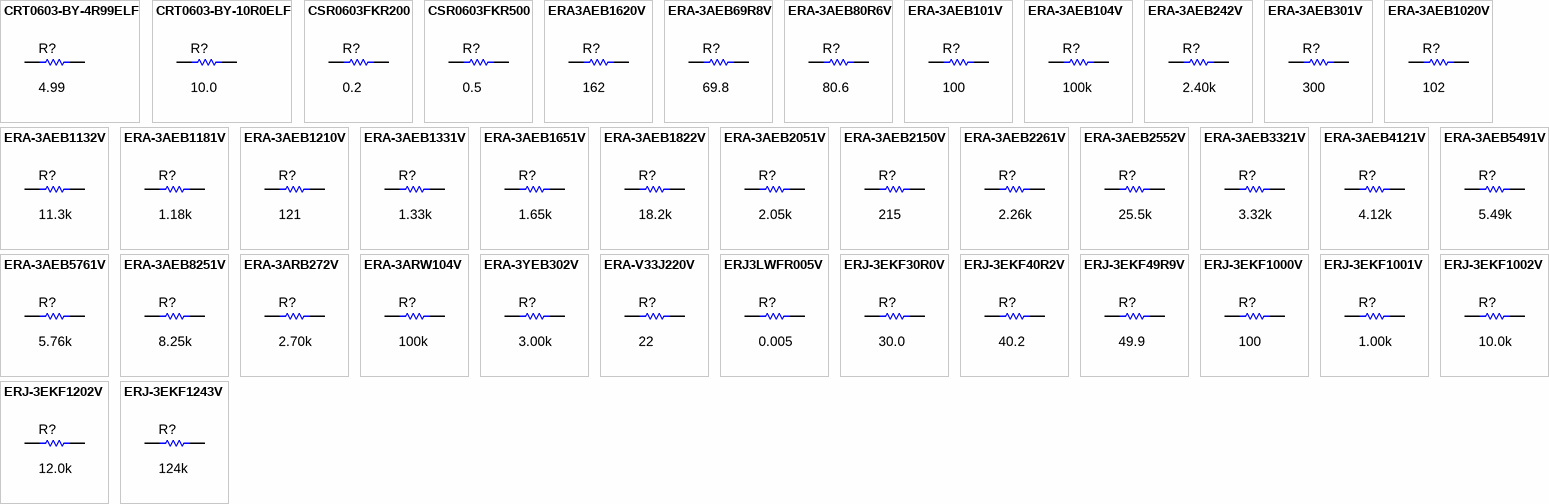
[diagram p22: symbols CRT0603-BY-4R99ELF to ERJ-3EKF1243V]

## CRT0603-BY-4R99ELF
designator R?  ValueDisplayed: 4.99  (hidden comment: CRT0603-BY-4R99ELF)
RES, 4.99, 0.1%, 0.1 W, 0603; Manufacturer: Bourns; CompType: Resistor; Value: 4.99; Value_Code: 4R99; Tolerance_%: 0.1; Value2: 0.1W; TempCo: 25 ppm/C; SizeArea_mm2: 1.28; SizeX_mm: 1.6; SizeY_mm: 0.8; SizeZ_mm: 1; EIA_Code: E192; U/M: EA; AEC Category: Q200; AEC Qualified: N
signal-integrity model Resistor
simulation model Resistor
footprint 0603
footprint 0603M
footprint 0603L
footprint 0603_HV
footprint 0603S
pins: 1, 2

## CRT0603-BY-10R0ELF
designator R?  ValueDisplayed: 10.0  (hidden comment: CRT0603-BY-10R0ELF)
RES, 10.0, 0.1%, 0.1 W, 0603; Manufacturer: Bourns; CompType: Resistor; Value: 10.0; Res_ohm: 10; Value_Code: 10R0; Tolerance_%: 0.1; Value2: 0.1W; TempCo: 25 ppm/C; SizeArea_mm2: 1.28; SizeX_mm: 1.6; SizeY_mm: 0.8; SizeZ_mm: 1; EIA_Code: E192; U/M: EA; AEC Category: Q200; AEC Qualified: N; Green_Lifecycle: Active; Green_REACh: Passed
signal-integrity model Resistor
simulation model Resistor
footprint 0603
footprint 0603M
footprint 0603L
footprint 0603_HV
footprint 0603S
pins: 1, 2

## CSR0603FKR200
designator R?  ValueDisplayed: 0.2  (hidden comment: CSR0603FKR200)
RES, 0.2, 1%, 0.125 W, 0603; Manufacturer: Stackpole Electronics Inc; CompType: Resistor; Value: 0.2; Value_Code: R200; Tolerance_%: 1; Power_W: 0.125; Value2: 0.125W; VDC_V: 300; TempCo: 25 ppm/C; SizeArea_mm2: 1.28; SizeX_mm: 1.6; SizeY_mm: 0.8; EIA_Code: E96; U/M: EA; AEC Category: Q200; AEC Qualified: N
signal-integrity model Resistor
simulation model Resistor
footprint 0603
footprint 0603M
footprint 0603L
footprint 0603_HV
footprint 0603S
pins: 1, 2

## CSR0603FKR500
designator R?  ValueDisplayed: 0.5  (hidden comment: CSR0603FKR500)
RES, 0.5, 1%, 0.125 W, 0603; Manufacturer: Stackpole Electronics Inc; CompType: Resistor; Value: 0.5; Value_Code: R500; Tolerance_%: 1; Power_W: 0.125; Value2: 0.125W; VDC_V: 200; TempCo: 300 ppm/C; SizeArea_mm2: 1.28; SizeX_mm: 1.6; SizeY_mm: 0.8; U/M: EA; AEC Category: Q200; Green_Lifecycle: Active; Green_REACh: Passed
signal-integrity model Resistor
simulation model Resistor
footprint 0603
footprint 0603M
footprint 0603L
footprint 0603_HV
footprint 0603S
pins: 1, 2

## ERA3AEB1620V
designator R?  ValueDisplayed: 162  (hidden comment: ERA3AEB1620V)
RES, 162, 0.1%, 0.1 W, AEC-Q200 Grade 0, 0603; Manufacturer: Panasonic; CompType: Resistor; Value: 162; Value_Code: 162R; Tolerance_%: 0.1; Value2: 0.1W; VDC_V: 75; TempCo: 25 ppm/C; SizeArea_mm2: 1.28; SizeX_mm: 1.6; SizeY_mm: 0.8; SizeZ_mm: 1; EIA_Code: E192; U/M: EA; AEC Category: Q200; AEC Qualified: Y; AEC Grade: 0
signal-integrity model Resistor
simulation model Resistor
footprint 0603
footprint 0603M
footprint 0603L
footprint 0603_HV
footprint 0603S
pins: 1, 2

## ERA-3AEB69R8V
designator R?  ValueDisplayed: 69.8  (hidden comment: ERA-3AEB69R8V)
RES, 69.8, 0.1%, 0.1 W, 0603; Manufacturer: Panasonic; CompType: Resistor; Value: 69.8; Value_Code: 69R8; Tolerance_%: 0.1; Value2: 0.1W; VDC_V: 75; TempCo: 25 ppm/C; SizeArea_mm2: 1.28; SizeX_mm: 1.6; SizeY_mm: 0.8; SizeZ_mm: 1; EIA_Code: E192; U/M: EA; AEC Category: Q200
signal-integrity model Resistor
simulation model Resistor
footprint 0603
footprint 0603M
footprint 0603L
footprint 0603_HV
footprint 0603S
pins: 1, 2

## ERA-3AEB80R6V
designator R?  ValueDisplayed: 80.6  (hidden comment: ERA-3AEB80R6V)
RES, 80.6, 0.1%, 0.1 W, AEC-Q200 Grade 0, 0603; Manufacturer: Panasonic; CompType: Resistor; Value: 80.6; Value_Code: 80R6; Tolerance_%: 0.1; Value2: 0.1W; VDC_V: 75; TempCo: 25 ppm/C; SizeArea_mm2: 1.28; SizeX_mm: 1.6; SizeY_mm: 0.8; SizeZ_mm: 1; EIA_Code: E192; U/M: EA; AEC Category: Q200; AEC Qualified: Y; AEC Grade: 0
signal-integrity model Resistor
simulation model Resistor
footprint 0603
footprint 0603M
footprint 0603L
footprint 0603_HV
footprint 0603S
pins: 1, 2

## ERA-3AEB101V
designator R?  ValueDisplayed: 100  (hidden comment: ERA-3AEB101V)
RES, 100, 0.1%, 0.1 W, AEC-Q200 Grade 0, 0603; Manufacturer: Panasonic; CompType: Resistor; Value: 100; Value_Code: 100R; Tolerance_%: 0.1; Value2: 0.1W; VDC_V: 75; TempCo: 25 ppm/C; SizeArea_mm2: 1.28; SizeX_mm: 1.6; SizeY_mm: 0.8; SizeZ_mm: 1; EIA_Code: E192; U/M: EA; AEC Category: Q200; AEC Qualified: Y; AEC Grade: 0; Green_Lifecycle: Active; Green_REACh: Passed
signal-integrity model Resistor
simulation model Resistor
footprint 0603
footprint 0603M
footprint 0603L
footprint 0603_HV
footprint 0603S
pins: 1, 2

## ERA-3AEB104V
designator R?  ValueDisplayed: 100k  (hidden comment: ERA-3AEB104V)
RES, 100 k, 0.1%, 0.1 W, AEC-Q200 Grade 0, 0603; Manufacturer: Panasonic; CompType: Resistor; Value: 100k; Res_ohm: 100000; Tolerance_%: 0.1; Value2: 0.1W; VDC_V: 75; TempCo: 25 ppm/C; SizeArea_mm2: 1.28; SizeX_mm: 1.6; SizeY_mm: 0.8; SizeZ_mm: 1; EIA_Code: E192; U/M: EA; AEC Category: Q200; AEC Qualified: Y; AEC Grade: 0
signal-integrity model Resistor
simulation model Resistor
footprint 0603
footprint 0603M
footprint 0603L
footprint 0603_HV
footprint 0603S
pins: 1, 2

## ERA-3AEB242V
designator R?  ValueDisplayed: 2.40k  (hidden comment: ERA-3AEB242V)
RES, 2.40 k, 0.1%, 0.1 W, AEC-Q200 Grade 0, 0603; Manufacturer: Panasonic; CompType: Resistor; Value: 2.40k; Res_ohm: 2400; Value_Code: 2k40; Tolerance_%: 0.1; Value2: 0.1W; VDC_V: 75; TempCo: 25 ppm/C; SizeArea_mm2: 1.28; SizeX_mm: 1.6; SizeY_mm: 0.8; SizeZ_mm: 1; EIA_Code: E192; U/M: EA; AEC Category: Q200; AEC Qualified: Y; AEC Grade: 0; Green_Lifecycle: Active; Green_REACh: Passed
signal-integrity model Resistor
simulation model Resistor
footprint 0603
footprint 0603M
footprint 0603L
footprint 0603_HV
footprint 0603S
pins: 1, 2

## ERA-3AEB301V
designator R?  ValueDisplayed: 300  (hidden comment: ERA-3AEB301V)
RES, 300, 0.1%, 0.1 W, AEC-Q200 Grade 0, 0603; Manufacturer: Panasonic; CompType: Resistor; Value: 300; Value_Code: 300R; Tolerance_%: 0.1; Value2: 0.1W; VDC_V: 75; TempCo: 25 ppm/C; SizeArea_mm2: 1.28; SizeX_mm: 1.6; SizeY_mm: 0.8; SizeZ_mm: 1; U/M: EA; AEC Category: Q200; AEC Qualified: Y; AEC Grade: 0
signal-integrity model Resistor
simulation model Resistor
footprint 0603
footprint 0603M
footprint 0603L
footprint 0603_HV
footprint 0603S
pins: 1, 2

## ERA-3AEB1020V
designator R?  ValueDisplayed: 102  (hidden comment: ERA-3AEB1020V)
RES, 102, 0.1%, 0.1 W, AEC-Q200 Grade 0, 0603; Manufacturer: Panasonic; CompType: Resistor; Value: 102; Value_Code: 102R; Tolerance_%: 0.1; Value2: 0.1W; VDC_V: 75; TempCo: 25 ppm/C; SizeArea_mm2: 1.28; SizeX_mm: 1.6; SizeY_mm: 0.8; SizeZ_mm: 1; EIA_Code: E192; U/M: EA; AEC Category: Q200; AEC Qualified: Y; AEC Grade: 0
signal-integrity model Resistor
simulation model Resistor
footprint 0603
footprint 0603M
footprint 0603L
footprint 0603_HV
footprint 0603S
pins: 1, 2

## ERA-3AEB1132V
designator R?  ValueDisplayed: 11.3k  (hidden comment: ERA-3AEB1132V)
RES, 11.3 k, 0.1%, 0.1 W, AEC-Q200 Grade 0, 0603; Manufacturer: Panasonic; CompType: Resistor; Value: 11.3k; Res_ohm: 11300; Value_Code: 11k3; Tolerance_%: 0.1; Value2: 0.1W; VDC_V: 75; TempCo: 25 ppm/C; SizeArea_mm2: 1.28; SizeX_mm: 1.6; SizeY_mm: 0.8; SizeZ_mm: 1; EIA_Code: E192; U/M: EA; AEC Category: Q200; AEC Qualified: Y; AEC Grade: 0
signal-integrity model Resistor
simulation model Resistor
footprint 0603
footprint 0603M
footprint 0603L
footprint 0603_HV
footprint 0603S
pins: 1, 2

## ERA-3AEB1181V
designator R?  ValueDisplayed: 1.18k  (hidden comment: ERA-3AEB1181V)
RES, 1.18 k, 0.1%, 0.1 W, AEC-Q200 Grade 0, 0603; Manufacturer: Panasonic; CompType: Resistor; Value: 1.18k; Res_ohm: 1180; Value_Code: 1k18; Tolerance_%: 0.1; Value2: 0.1W; VDC_V: 75; TempCo: 25 ppm/C; SizeArea_mm2: 1.28; SizeX_mm: 1.6; SizeY_mm: 0.8; SizeZ_mm: 1; EIA_Code: E192; U/M: EA; AEC Category: Q200; AEC Qualified: Y; AEC Grade: 0; Green_Lifecycle: Active; Green_REACh: Passed
signal-integrity model Resistor
simulation model Resistor
footprint 0603
footprint 0603M
footprint 0603L
footprint 0603_HV
footprint 0603S
pins: 1, 2

## ERA-3AEB1210V
designator R?  ValueDisplayed: 121  (hidden comment: ERA-3AEB1210V)
RES, 121, 0.1%, 0.1 W, AEC-Q200 Grade 0, 0603; Manufacturer: Panasonic; CompType: Resistor; Value: 121; Value_Code: 121R; Tolerance_%: 0.1; Value2: 0.1W; VDC_V: 75; TempCo: 25 ppm/C; SizeArea_mm2: 1.28; SizeX_mm: 1.6; SizeY_mm: 0.8; SizeZ_mm: 1; EIA_Code: E192; U/M: EA; AEC Category: Q200; AEC Qualified: Y; AEC Grade: 0
signal-integrity model Resistor
simulation model Resistor
footprint 0603
footprint 0603M
footprint 0603L
footprint 0603_HV
footprint 0603S
pins: 1, 2

## ERA-3AEB1331V
designator R?  ValueDisplayed: 1.33k  (hidden comment: ERA-3AEB1331V)
RES, 1.33 k, 0.1%, 0.1 W, AEC-Q200 Grade 0, 0603; Manufacturer: Panasonic; CompType: Resistor; Value: 1.33k; Res_ohm: 1330; Value_Code: 1k33; Tolerance_%: 0.1; Value2: 0.1W; VDC_V: 75; TempCo: 25 ppm/C; SizeArea_mm2: 1.28; SizeX_mm: 1.6; SizeY_mm: 0.8; SizeZ_mm: 1; EIA_Code: E192; U/M: EA; AEC Category: Q200; AEC Qualified: Y; AEC Grade: 0
signal-integrity model Resistor
simulation model Resistor
footprint 0603
footprint 0603M
footprint 0603L
footprint 0603_HV
footprint 0603S
pins: 1, 2

## ERA-3AEB1651V
designator R?  ValueDisplayed: 1.65k  (hidden comment: ERA-3AEB1651V)
RES, 1.65 k, 0.1%, 0.1 W, AEC-Q200 Grade 0, 0603; Manufacturer: Panasonic; CompType: Resistor; Value: 1.65k; Res_ohm: 1650; Value_Code: 1k65; Tolerance_%: 0.1; Value2: 0.1W; VDC_V: 75; TempCo: 25 ppm/C; SizeArea_mm2: 1.28; SizeX_mm: 1.6; SizeY_mm: 0.8; SizeZ_mm: 1; EIA_Code: E192; U/M: EA; AEC Category: Q200; AEC Qualified: Y; AEC Grade: 0
signal-integrity model Resistor
simulation model Resistor
footprint 0603
footprint 0603M
footprint 0603L
footprint 0603_HV
footprint 0603S
pins: 1, 2

## ERA-3AEB1822V
designator R?  ValueDisplayed: 18.2k  (hidden comment: ERA-3AEB1822V)
RES, 18.2 k, 0.1%, 0.1 W, AEC-Q200 Grade 0, 0603; Manufacturer: Panasonic; CompType: Resistor; Value: 18.2k; Res_ohm: 18200; Value_Code: 18k2; Tolerance_%: 0.1; Value2: 0.1W; VDC_V: 75; TempCo: 25 ppm/C; SizeArea_mm2: 1.28; SizeX_mm: 1.6; SizeY_mm: 0.8; SizeZ_mm: 1; EIA_Code: E192; U/M: EA; AEC Category: Q200; AEC Qualified: Y; AEC Grade: 0
signal-integrity model Resistor
simulation model Resistor
footprint 0603
footprint 0603M
footprint 0603L
footprint 0603_HV
footprint 0603S
pins: 1, 2

## ERA-3AEB2051V
designator R?  ValueDisplayed: 2.05k  (hidden comment: ERA-3AEB2051V)
RES, 2.05 k, 0.1%, 0.1 W, AEC-Q200 Grade 0, 0603; Manufacturer: Panasonic; CompType: Resistor; Value: 2.05k; Res_ohm: 2050; Value_Code: 2k05; Tolerance_%: 0.1; Value2: 0.1W; VDC_V: 75; TempCo: 25 ppm/C; SizeArea_mm2: 1.28; SizeX_mm: 1.6; SizeY_mm: 0.8; SizeZ_mm: 1; EIA_Code: E192; U/M: EA; AEC Category: Q200; AEC Qualified: Y; AEC Grade: 0
signal-integrity model Resistor
simulation model Resistor
footprint 0603
footprint 0603M
footprint 0603L
footprint 0603_HV
footprint 0603S
pins: 1, 2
